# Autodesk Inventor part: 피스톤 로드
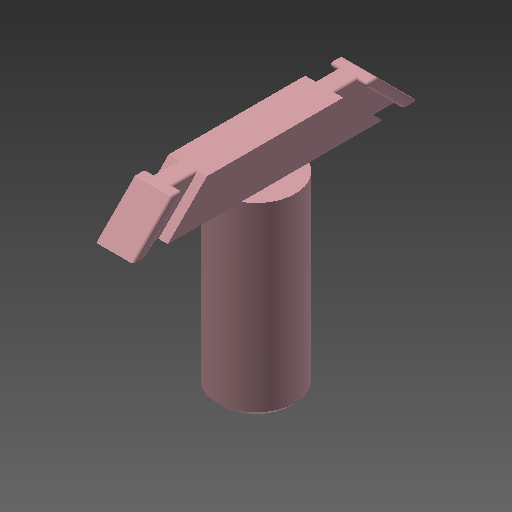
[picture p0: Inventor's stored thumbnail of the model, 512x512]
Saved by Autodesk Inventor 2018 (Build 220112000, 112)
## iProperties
Created: 2023-03
Part Number: 피스톤 로드
Material: 강철, 연강
Document SubType Name: Modeling
Designer: mdu-01
Density: 1 g/cm^3
Appearance: 기본값(1)
Author: mdu-01
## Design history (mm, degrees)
sketch "스케치1"
  geometry: L1 (0, 0)-(0, 29); L2 (0, 29)-(8, 21); L3 (8, 21)-(8, 0); L4 (8, 0)-(0, 0); L5 (0, 26.172)-(8, 18.172); L6 (0, 21.929)-(8, 13.929)
  constraints: 12 end point, 4 point on line, 3 parallel, 1 perpendicular, 1 vertical
  dimensions: "d0" = 45 deg angle of L1 L2; "d1" = 29 distance of L1.start L1.end; "d2" = 8 distance between parallel lines of L3 L1; "d3" = 2 distance between parallel lines of L5 L2; "d4" = 3 distance between parallel lines of L6 L5
extrude "돌출1" new body sketch "스케치1" stored distance "d5" = 7.8; taper "d6" = 0 deg
extrude "돌출2" join sketch "스케치1" stored distance "d7" = 4; taper "d8" = 0 deg
fillet "모깎기5" dims "d31" = 0.5
sketch "스케치3"
  geometry: C1 r 8 at (-2, -21.929); 1 further point
  constraints: 1 centre point, 1 coincident
  dimensions: "d32" = 16 diameter of C1
extrude "돌출4" join sketch "스케치3" distance "d33" = 38; taper "d34" = 0 deg
chamfer "모따기2" distance "d35" = 1; stored, may be unused: second distance "d36" = 2, angle "d37" = 45 deg
hole "구멍2" diameter "d40" = 4.917; stored, may be unused: countersink angle "d44" = 90 deg, drill point angle "d46" = 118 deg; dims "d41" = 12, "d42" = 4, "d43" = 2, "d45" = 14, "d47" = 10, "d48" = 10
node "솔리드1"
pattern_circular "원형 패턴1" dims angle "d12" = 360 deg
